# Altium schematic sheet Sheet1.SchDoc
size A
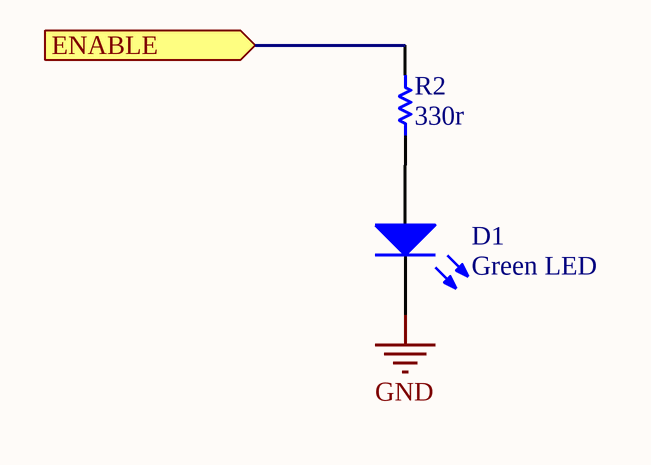
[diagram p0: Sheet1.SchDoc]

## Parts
D1  Green LED  [LED-0]
R2  330r  [AXIAL-0.3]

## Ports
ENABLE (in)

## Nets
GND: D1.2(K)
ENABLE: R2.2 ; port ENABLE
NetD1_1: D1.1(A) R2.1

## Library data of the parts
D1 = LED0: Typical INFRARED GaAs LED
R2 = Res1: Resistor; Value: 1K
